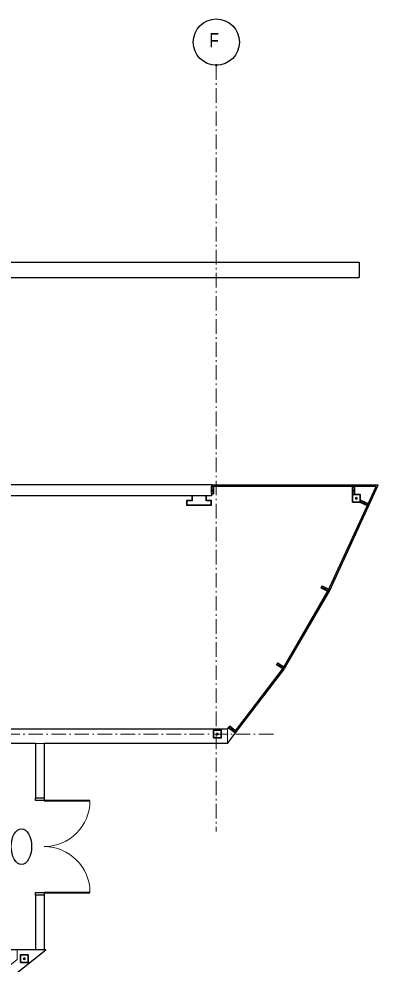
# Model space of a CAD drawing. Extents: x 10076 to 10305, y 10052 to 10157.
# Drawn here: x 10211.3 to 10234.7, y 10095.4 to 10157.1 of the extents above; entities that cross this region are included whole.
import ezdxf
from ezdxf.enums import TextEntityAlignment as Align

# ---------------------------------------------------------------- set-up
doc = ezdxf.new("R2010")
doc.units = 0
doc.header["$LTSCALE"] = 0.19
doc.header["$PDMODE"] = 32
doc.header["$PDSIZE"] = 0.095
doc.linetypes.add('DOT_DASHED', pattern=[7.7, 5, -1.2, 0.3, -1.2])
for name, color, linetype, lineweight in [('1', 7, 'Continuous', 13), ('10', 7, 'DOT_DASHED', 13), ('11', 7, 'Continuous', 25), ('12', 7, 'Continuous', 35), ('23', 7, 'Continuous', 25), ('25', 7, 'Continuous', 13), ('26', 7, 'Continuous', 25), ('42', 7, 'Continuous', 25)]:
    doc.layers.add(name, color=color, linetype=linetype, lineweight=lineweight)

msp = doc.modelspace()

# ---------------------------------------------------------------- linework, layer by layer
at = {"layer": '1'}
for p, q in [((10234.069, 10125.4281), (10231.4856, 10119.8253)), ((10228.5475, 10114.7708), (10231.4856, 10119.8253)), ((10228.5475, 10114.7708), (10225.3538, 10110.5807))]:
    msp.add_line(p, q, dxfattribs=at)
for points in [[(10188.169, 10141.2504), (10188.169, 10140.2504), (10233.4943, 10140.2504), (10233.4943, 10141.2504)], [(10204.9242, 10126.7087), (10204.9242, 10125.99), (10223.8513, 10125.99), (10223.8513, 10126.7087)], [(10223.9763, 10126.6046), (10223.9763, 10126.1254), (10223.8513, 10126.1254), (10223.8513, 10126.6046)], [(10233.07, 10126.6046), (10233.07, 10126.0837), (10233.195, 10126.0837), (10233.195, 10126.6046)], [(10222.5596, 10125.99), (10222.5596, 10125.6983), (10222.2263, 10125.6983), (10222.2263, 10125.3858), (10223.8513, 10125.3858), (10223.8513, 10125.6983), (10223.5179, 10125.6983), (10223.5179, 10125.99)], [(10233.07, 10125.5837), (10233.07, 10126.0837), (10233.57, 10126.0837), (10233.57, 10125.5837)], [(10233.6215, 10125.6972), (10233.5687, 10125.5839), (10234.0407, 10125.3638), (10234.0936, 10125.4771)], [(10231.0841, 10120.1033), (10231.0273, 10119.9918), (10231.4542, 10119.7743), (10231.511, 10119.8857)], [(10228.1791, 10115.0912), (10228.1111, 10114.9864), (10228.5129, 10114.7254), (10228.581, 10114.8302)], [(10224.8926, 10110.766), (10224.9727, 10110.8711), (10225.4201, 10110.5301), (10224.9012, 10109.8493)], [(10225.0488, 10110.9703), (10224.9727, 10110.8711), (10225.3538, 10110.5807), (10225.429, 10110.6786)], [(10204.9242, 10109.8493), (10204.9242, 10110.766), (10224.8926, 10110.766), (10224.8926, 10109.8493)], [(10212.3513, 10109.8493), (10212.3513, 10106.2817), (10212.9138, 10106.2817), (10212.9138, 10109.8493)], [(10212.3513, 10099.9484), (10212.3513, 10096.3806), (10212.9138, 10096.3806), (10212.9138, 10099.9484)], [(10211.1603, 10096.3806), (10213.0179, 10096.3806), (10206.1076, 10090.8876), (10205.6117, 10090.8858), (10205.6117, 10091.6266), (10205.9659, 10091.6266), (10211.1603, 10095.7556)]]:
    msp.add_lwpolyline(points, close=True, dxfattribs=at)
at = {"layer": '10'}
for p, q in [((10224.169, 10154.0964), (10224.169, 10104.0964)), ((10227.8946, 10110.4431), (10179.5805, 10110.4431))]:
    msp.add_line(p, q, dxfattribs=at)
msp.add_point((10224.169, 10154.0964), dxfattribs=at)
at = {"layer": '11'}
msp.add_circle((10224.169, 10155.6074), 1.511, dxfattribs=at)
at = {"layer": '12'}
for points in [[(10223.8513, 10126.1254), (10223.8513, 10126.6046), (10223.9763, 10126.6046), (10223.9763, 10126.1254)], [(10233.07, 10126.0837), (10233.07, 10126.6046), (10233.195, 10126.6046), (10233.195, 10126.0837)], [(10233.07, 10125.5837), (10233.07, 10126.0837), (10233.57, 10126.0837), (10233.57, 10125.5837)], [(10234.0407, 10125.3638), (10233.5687, 10125.5839), (10233.6215, 10125.6972), (10234.0936, 10125.4771)], [(10231.4542, 10119.7743), (10231.0273, 10119.9918), (10231.0841, 10120.1033), (10231.511, 10119.8857)], [(10228.5129, 10114.7254), (10228.1111, 10114.9864), (10228.1791, 10115.0912), (10228.581, 10114.8302)], [(10225.3529, 10110.5794), (10224.9727, 10110.8711), (10225.0488, 10110.9703), (10225.429, 10110.6786)], [(10223.9867, 10110.2035), (10223.9867, 10110.7035), (10224.4867, 10110.7035), (10224.4867, 10110.2035)], [(10211.3721, 10095.5473), (10211.3721, 10096.0473), (10211.8721, 10096.0473), (10211.8721, 10095.5473)]]:
    msp.add_lwpolyline(points, close=True, dxfattribs=at)
for p in [(10223.9138, 10126.365), (10233.1325, 10126.3441), (10233.32, 10125.8337), (10233.8311, 10125.5305), (10231.2691, 10119.9388), (10228.346, 10114.9083), (10225.2008, 10110.7749), (10224.2367, 10110.4535), (10211.6221, 10095.7973)]:
    msp.add_point(p, dxfattribs=at)
at = {"layer": '23'}
for p, q in [((10188.169, 10141.2504), (10233.4943, 10141.2504)), ((10233.4943, 10141.2504), (10233.4943, 10140.2504)), ((10206.1742, 10140.2504), (10233.4943, 10140.2504)), ((10223.8513, 10126.7087), (10206.1742, 10126.7087)), ((10223.8513, 10126.7087), (10223.8513, 10125.99)), ((10223.8513, 10126.6879), (10223.8513, 10126.6046)), ((10234.7417, 10126.6879), (10223.8513, 10126.6879)), ((10234.6115, 10126.6046), (10223.8513, 10126.6046)), ((10231.4856, 10119.8253), (10234.6115, 10126.6046)), ((10231.5612, 10119.7904), (10234.7417, 10126.6879)), ((10222.5596, 10125.99), (10205.3304, 10125.99)), ((10222.5596, 10125.6983), (10222.2263, 10125.6983)), ((10222.2263, 10125.6983), (10222.2263, 10125.3858)), ((10222.5804, 10125.6775), (10222.2471, 10125.6775)), ((10222.2471, 10125.6775), (10222.2471, 10125.4066)), ((10222.5596, 10125.99), (10222.5596, 10125.6983)), ((10222.5804, 10125.99), (10222.5804, 10125.6775)), ((10223.4971, 10125.99), (10222.5804, 10125.99)), ((10223.4971, 10125.6775), (10223.4971, 10125.99)), ((10223.8304, 10125.6775), (10223.4971, 10125.6775)), ((10223.5179, 10125.6983), (10223.5179, 10125.99)), ((10223.8513, 10125.99), (10223.5179, 10125.99)), ((10223.8513, 10125.6983), (10223.5179, 10125.6983)), ((10223.8304, 10125.4066), (10223.8304, 10125.6775)), ((10223.8513, 10125.3858), (10223.8513, 10125.6983)), ((10222.2263, 10125.3858), (10223.8513, 10125.3858)), ((10222.2471, 10125.4066), (10223.8304, 10125.4066)), ((10228.5475, 10114.7708), (10231.4856, 10119.8253)), ((10228.6196, 10114.7289), (10231.5576, 10119.7834)), ((10225.3538, 10110.5807), (10228.5475, 10114.7708)), ((10225.4201, 10110.5302), (10228.6138, 10114.7203)), ((10224.8926, 10110.766), (10224.9727, 10110.8711)), ((10224.9727, 10110.8711), (10225.4201, 10110.5301)), ((10224.8926, 10110.766), (10206.6534, 10110.766)), ((10224.9012, 10109.8493), (10225.4201, 10110.5301)), ((10225.3538, 10110.5807), (10225.4201, 10110.5302)), ((10212.3513, 10109.8493), (10205.3513, 10109.8493)), ((10212.3513, 10109.8493), (10212.3513, 10106.2817)), ((10224.9012, 10109.8493), (10212.9138, 10109.8493)), ((10212.9138, 10109.8493), (10212.9138, 10106.2817)), ((10212.9138, 10106.2817), (10212.3513, 10106.2817)), ((10212.3513, 10099.9484), (10212.3513, 10096.3806)), ((10212.9138, 10099.9484), (10212.3513, 10099.9484)), ((10212.9138, 10099.9484), (10212.9138, 10096.3806)), ((10213.0179, 10096.3806), (10205.3513, 10096.3806)), ((10206.1076, 10090.8876), (10213.0179, 10096.3806)), ((10212.9138, 10096.3806), (10212.3513, 10096.3806))]:
    msp.add_line(p, q, dxfattribs=at)
at = {"layer": '25', "lineweight": 40}
for p, q in [((10212.9138, 10106.1151), (10215.9138, 10106.1151)), ((10212.9138, 10100.1149), (10215.9139, 10100.1149))]:
    msp.add_line(p, q, dxfattribs=at)
at = {"layer": '25'}
for centre, start, end in [((10212.9138, 10106.1151), 270.00005, 359.99974), ((10212.9138, 10100.1149), 0.00025, 89.99995)]:
    msp.add_arc(centre, 3.0001, start, end, dxfattribs=at)
at = {"layer": '26'}
for points in [[(10212.9138, 10106.2817), (10212.9138, 10106.1151), (10212.3513, 10106.1151), (10212.3513, 10106.2817)], [(10212.3513, 10099.9484), (10212.3513, 10100.1151), (10212.9138, 10100.1151), (10212.9138, 10099.9484)]]:
    msp.add_lwpolyline(points, dxfattribs=at)
at = {"layer": '42'}
msp.add_ellipse((10211.4346, 10103.1151), major_axis=(0, -1.1667), ratio=0.571429, dxfattribs=at)

# ---------------------------------------------------------------- texts
at = {"layer": '11', "width": 0.8}
msp.add_text('F', height=0.9412, dxfattribs=at).set_placement((10224.0274, 10155.2531), align=Align.CENTER)

doc.saveas('drawing.dxf')
